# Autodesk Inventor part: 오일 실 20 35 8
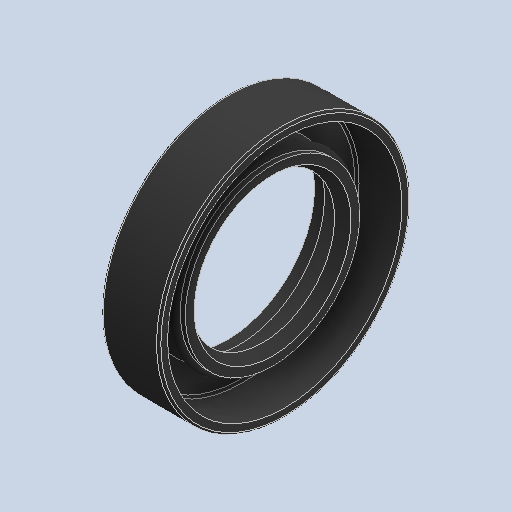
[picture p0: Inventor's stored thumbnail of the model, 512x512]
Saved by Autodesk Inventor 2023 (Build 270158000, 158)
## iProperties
Created: 2026-06
Part Number: 오일 실 20 35 8
Material: 고무
Description: 오일-실
Document SubType Name: Modeling
Designer: home
Density: 0.93 g/cm^3
Appearance: 기본값
Sending System: Autodesk Inventor 2027
Preprocessor: ST-DEVELOPER v20.1
Author: jhkim
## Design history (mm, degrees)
feature "Solid1"
node "솔리드1"
